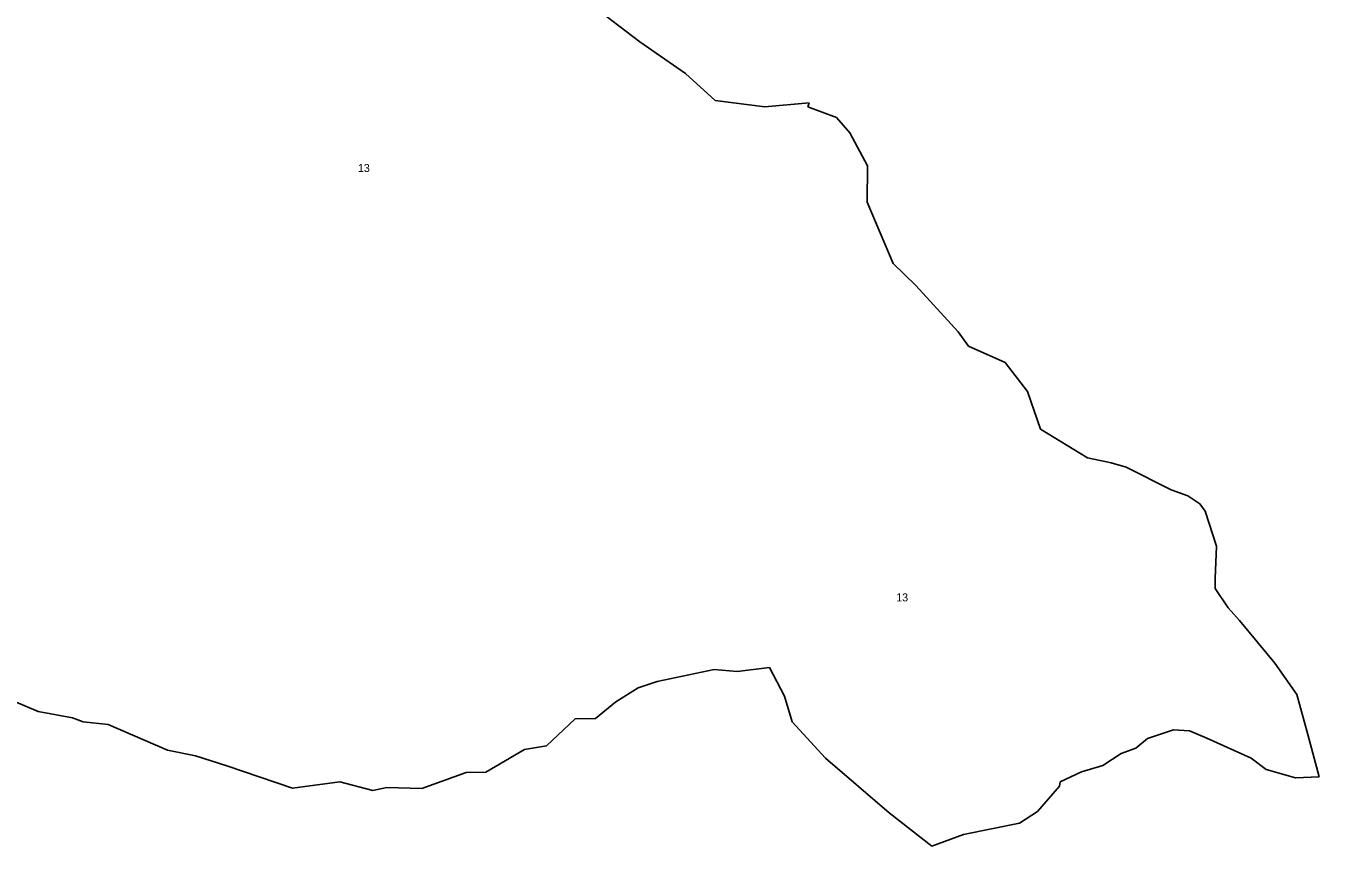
# Model space of a CAD drawing. Extents: x -790709 to -785360, y -974907 to -970918.
# Drawn here: x -786976 to -785360, y -973935 to -972910 of the extents above; entities that cross this region are included whole.
import ezdxf

# ---------------------------------------------------------------- set-up
doc = ezdxf.new("R2010")
doc.units = 0
doc.layers.add('Vrstva 13', color=7, linetype='Continuous')
doc.layers.add('Vrstva 63', color=7, linetype='Continuous')

msp = doc.modelspace()

# ---------------------------------------------------------------- linework, layer by layer
at = {"layer": 'Vrstva 13'}
for p, q in [((-786208.8, -972929.6), (-786261.2, -972889.8)), ((-786151.7, -972969.2), (-786208.8, -972929.6)), ((-786114.4, -973003.2), (-786151.7, -972969.2)), ((-786052.6, -973010.8), (-786114.4, -973003.2)), ((-785997.1, -973006.1), (-786052.6, -973010.8)), ((-785998.7, -973011), (-785997.1, -973006.1)), ((-785962.9, -973024.3), (-785998.7, -973011)), ((-785946.5, -973043.5), (-785962.9, -973024.3)), ((-785924.2, -973084.7), (-785946.5, -973043.5)), ((-785924.7, -973130.1), (-785924.2, -973084.7)), ((-785892.3, -973206.7), (-785924.7, -973130.1)), ((-785863.8, -973234.2), (-785892.3, -973206.7)), ((-785810.8, -973292.3), (-785863.8, -973234.2)), ((-785797.9, -973310), (-785810.8, -973292.3)), ((-785752.2, -973330.5), (-785797.9, -973310)), ((-785724.5, -973366.8), (-785752.2, -973330.5)), ((-785707.9, -973413.8), (-785724.5, -973366.8)), ((-785649.5, -973449.8), (-785707.9, -973413.8)), ((-785619.7, -973455.8), (-785649.5, -973449.8)), ((-785601, -973461.5), (-785619.7, -973455.8)), ((-785544.9, -973489.8), (-785601, -973461.5)), ((-785523.9, -973497.3), (-785544.9, -973489.8)), ((-785509.1, -973507.2), (-785523.9, -973497.3)), ((-785502.4, -973516.6), (-785509.1, -973507.2)), ((-785488.4, -973560.2), (-785502.4, -973516.6)), ((-785490, -973600.6), (-785488.4, -973560.2)), ((-785489.7, -973613.1), (-785490, -973600.6)), ((-785473.6, -973637.2), (-785489.7, -973613.1)), ((-785459.6, -973653.3), (-785473.6, -973637.2)), ((-785415.2, -973706.5), (-785459.6, -973653.3)), ((-786186.9, -973729.3), (-786115.8, -973714.5)), ((-786186.9, -973729.3), (-786115.8, -973714.5)), ((-786186.9, -973729.3), (-786115.8, -973714.5)), ((-786115.8, -973714.5), (-786087.2, -973716.8)), ((-786115.8, -973714.5), (-786087.2, -973716.8)), ((-786115.8, -973714.5), (-786087.2, -973716.8)), ((-786087.2, -973716.8), (-786046.7, -973711.8)), ((-786087.2, -973716.8), (-786046.7, -973711.8)), ((-786087.2, -973716.8), (-786046.7, -973711.8)), ((-786046.7, -973711.8), (-786028, -973747.6)), ((-786046.7, -973711.8), (-786028, -973747.6)), ((-786046.7, -973711.8), (-786028, -973747.6)), ((-785388, -973745.7), (-785415.2, -973706.5)), ((-786210.7, -973737.4), (-786186.9, -973729.3)), ((-786210.7, -973737.4), (-786186.9, -973729.3)), ((-786210.7, -973737.4), (-786186.9, -973729.3)), ((-786238.8, -973754.7), (-786210.7, -973737.4)), ((-786238.8, -973754.7), (-786210.7, -973737.4)), ((-786238.8, -973754.7), (-786210.7, -973737.4)), ((-786028, -973747.6), (-786018.5, -973779.6)), ((-786028, -973747.6), (-786018.5, -973779.6)), ((-786028, -973747.6), (-786018.5, -973779.6)), ((-785374, -973795.8), (-785388, -973745.7)), ((-786991, -973754), (-786960.6, -973766.9)), ((-786991, -973754), (-786960.6, -973766.9)), ((-786991, -973754), (-786960.6, -973766.9)), ((-786960.6, -973766.9), (-786917.4, -973774.9)), ((-786960.6, -973766.9), (-786917.4, -973774.9)), ((-786960.6, -973766.9), (-786917.4, -973774.9)), ((-786264.3, -973775.7), (-786238.8, -973754.7)), ((-786264.3, -973775.7), (-786238.8, -973754.7)), ((-786264.3, -973775.7), (-786238.8, -973754.7)), ((-786917.4, -973774.9), (-786904.4, -973779.9)), ((-786917.4, -973774.9), (-786904.4, -973779.9)), ((-786917.4, -973774.9), (-786904.4, -973779.9)), ((-786904.4, -973779.9), (-786873.2, -973783.2)), ((-786904.4, -973779.9), (-786873.2, -973783.2)), ((-786904.4, -973779.9), (-786873.2, -973783.2)), ((-786873.2, -973783.2), (-786798.7, -973815.3)), ((-786873.2, -973783.2), (-786798.7, -973815.3)), ((-786873.2, -973783.2), (-786798.7, -973815.3)), ((-786325.4, -973809.8), (-786289.6, -973776.1)), ((-786325.4, -973809.8), (-786289.6, -973776.1)), ((-786325.4, -973809.8), (-786289.6, -973776.1)), ((-786289.6, -973776.1), (-786264.3, -973775.7)), ((-786289.6, -973776.1), (-786264.3, -973775.7)), ((-786289.6, -973776.1), (-786264.3, -973775.7)), ((-786018.5, -973779.6), (-785976.8, -973825)), ((-786018.5, -973779.6), (-785976.8, -973825)), ((-786018.5, -973779.6), (-785976.8, -973825)), ((-785574.5, -973800.5), (-785542.1, -973789.6)), ((-785542.1, -973789.6), (-785522.1, -973791.1)), ((-785522.1, -973791.1), (-785500.3, -973800)), ((-785500.3, -973800), (-785445.1, -973825.4)), ((-785360, -973848.5), (-785374, -973795.8)), ((-786798.7, -973815.3), (-786763.8, -973822.3)), ((-786798.7, -973815.3), (-786763.8, -973822.3)), ((-786798.7, -973815.3), (-786763.8, -973822.3)), ((-786401.2, -973842.7), (-786352.9, -973814.4)), ((-786401.2, -973842.7), (-786352.9, -973814.4)), ((-786401.2, -973842.7), (-786352.9, -973814.4)), ((-786352.9, -973814.4), (-786325.4, -973809.8)), ((-786352.9, -973814.4), (-786325.4, -973809.8)), ((-786352.9, -973814.4), (-786325.4, -973809.8)), ((-785607.2, -973819.4), (-785589, -973812.9)), ((-785589, -973812.9), (-785574.5, -973800.5)), ((-786763.8, -973822.3), (-786724.6, -973834.8)), ((-786763.8, -973822.3), (-786724.6, -973834.8)), ((-786763.8, -973822.3), (-786724.6, -973834.8)), ((-785976.8, -973825), (-785897.3, -973893.7)), ((-785976.8, -973825), (-785897.3, -973893.7)), ((-785976.8, -973825), (-785897.3, -973893.7)), ((-785630.3, -973834.5), (-785607.2, -973819.4)), ((-785445.1, -973825.4), (-785426.1, -973839.4)), ((-786724.6, -973834.8), (-786642.6, -973862.7)), ((-786724.6, -973834.8), (-786642.6, -973862.7)), ((-786724.6, -973834.8), (-786642.6, -973862.7)), ((-786481.1, -973863.1), (-786425.8, -973843.2)), ((-786481.1, -973863.1), (-786425.8, -973843.2)), ((-786481.1, -973863.1), (-786425.8, -973843.2)), ((-786425.8, -973843.2), (-786401.2, -973842.7)), ((-786425.8, -973843.2), (-786401.2, -973842.7)), ((-786425.8, -973843.2), (-786401.2, -973842.7)), ((-785683.5, -973854.7), (-785656.7, -973842.5)), ((-785656.7, -973842.5), (-785630.3, -973834.5)), ((-785426.1, -973839.4), (-785389.6, -973850)), ((-785389.6, -973850), (-785360, -973848.5)), ((-786642.6, -973862.7), (-786583.5, -973854.8)), ((-786642.6, -973862.7), (-786583.5, -973854.8)), ((-786642.6, -973862.7), (-786583.5, -973854.8)), ((-786583.5, -973854.8), (-786542.3, -973865.6)), ((-786583.5, -973854.8), (-786542.3, -973865.6)), ((-786583.5, -973854.8), (-786542.3, -973865.6)), ((-786542.3, -973865.6), (-786524.8, -973861.9)), ((-786542.3, -973865.6), (-786524.8, -973861.9)), ((-786542.3, -973865.6), (-786524.8, -973861.9)), ((-786524.8, -973861.9), (-786481.1, -973863.1)), ((-786524.8, -973861.9), (-786481.1, -973863.1)), ((-786524.8, -973861.9), (-786481.1, -973863.1)), ((-785712, -973891.8), (-785684.5, -973860.4)), ((-785684.5, -973860.4), (-785683.5, -973854.7)), ((-785897.3, -973893.7), (-785843.7, -973935.2)), ((-785897.3, -973893.7), (-785843.7, -973935.2)), ((-785734.3, -973906.6), (-785712, -973891.8)), ((-785804.3, -973920.6), (-785734.3, -973906.6)), ((-785843.7, -973935.2), (-785804.3, -973920.6))]:
    msp.add_line(p, q, dxfattribs=at)

# ---------------------------------------------------------------- texts
at = {"layer": 'Vrstva 63'}
for p in [(-786561, -973092.4), (-785888.4, -973629.2)]:
    msp.add_text('13', height=10, dxfattribs=at).set_placement(p)

doc.saveas('drawing.dxf')
